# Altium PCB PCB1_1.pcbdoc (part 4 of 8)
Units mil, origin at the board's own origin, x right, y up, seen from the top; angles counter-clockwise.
Board outline 3937.01 x 3346.46 mil, 6 copper layers (Top Layer, Signal-1, SIG, POWER, Signal-4, Bottom Layer), stack 60.565 mil thick; 256 components, 201 nets, 1360 pads, 815 vias.
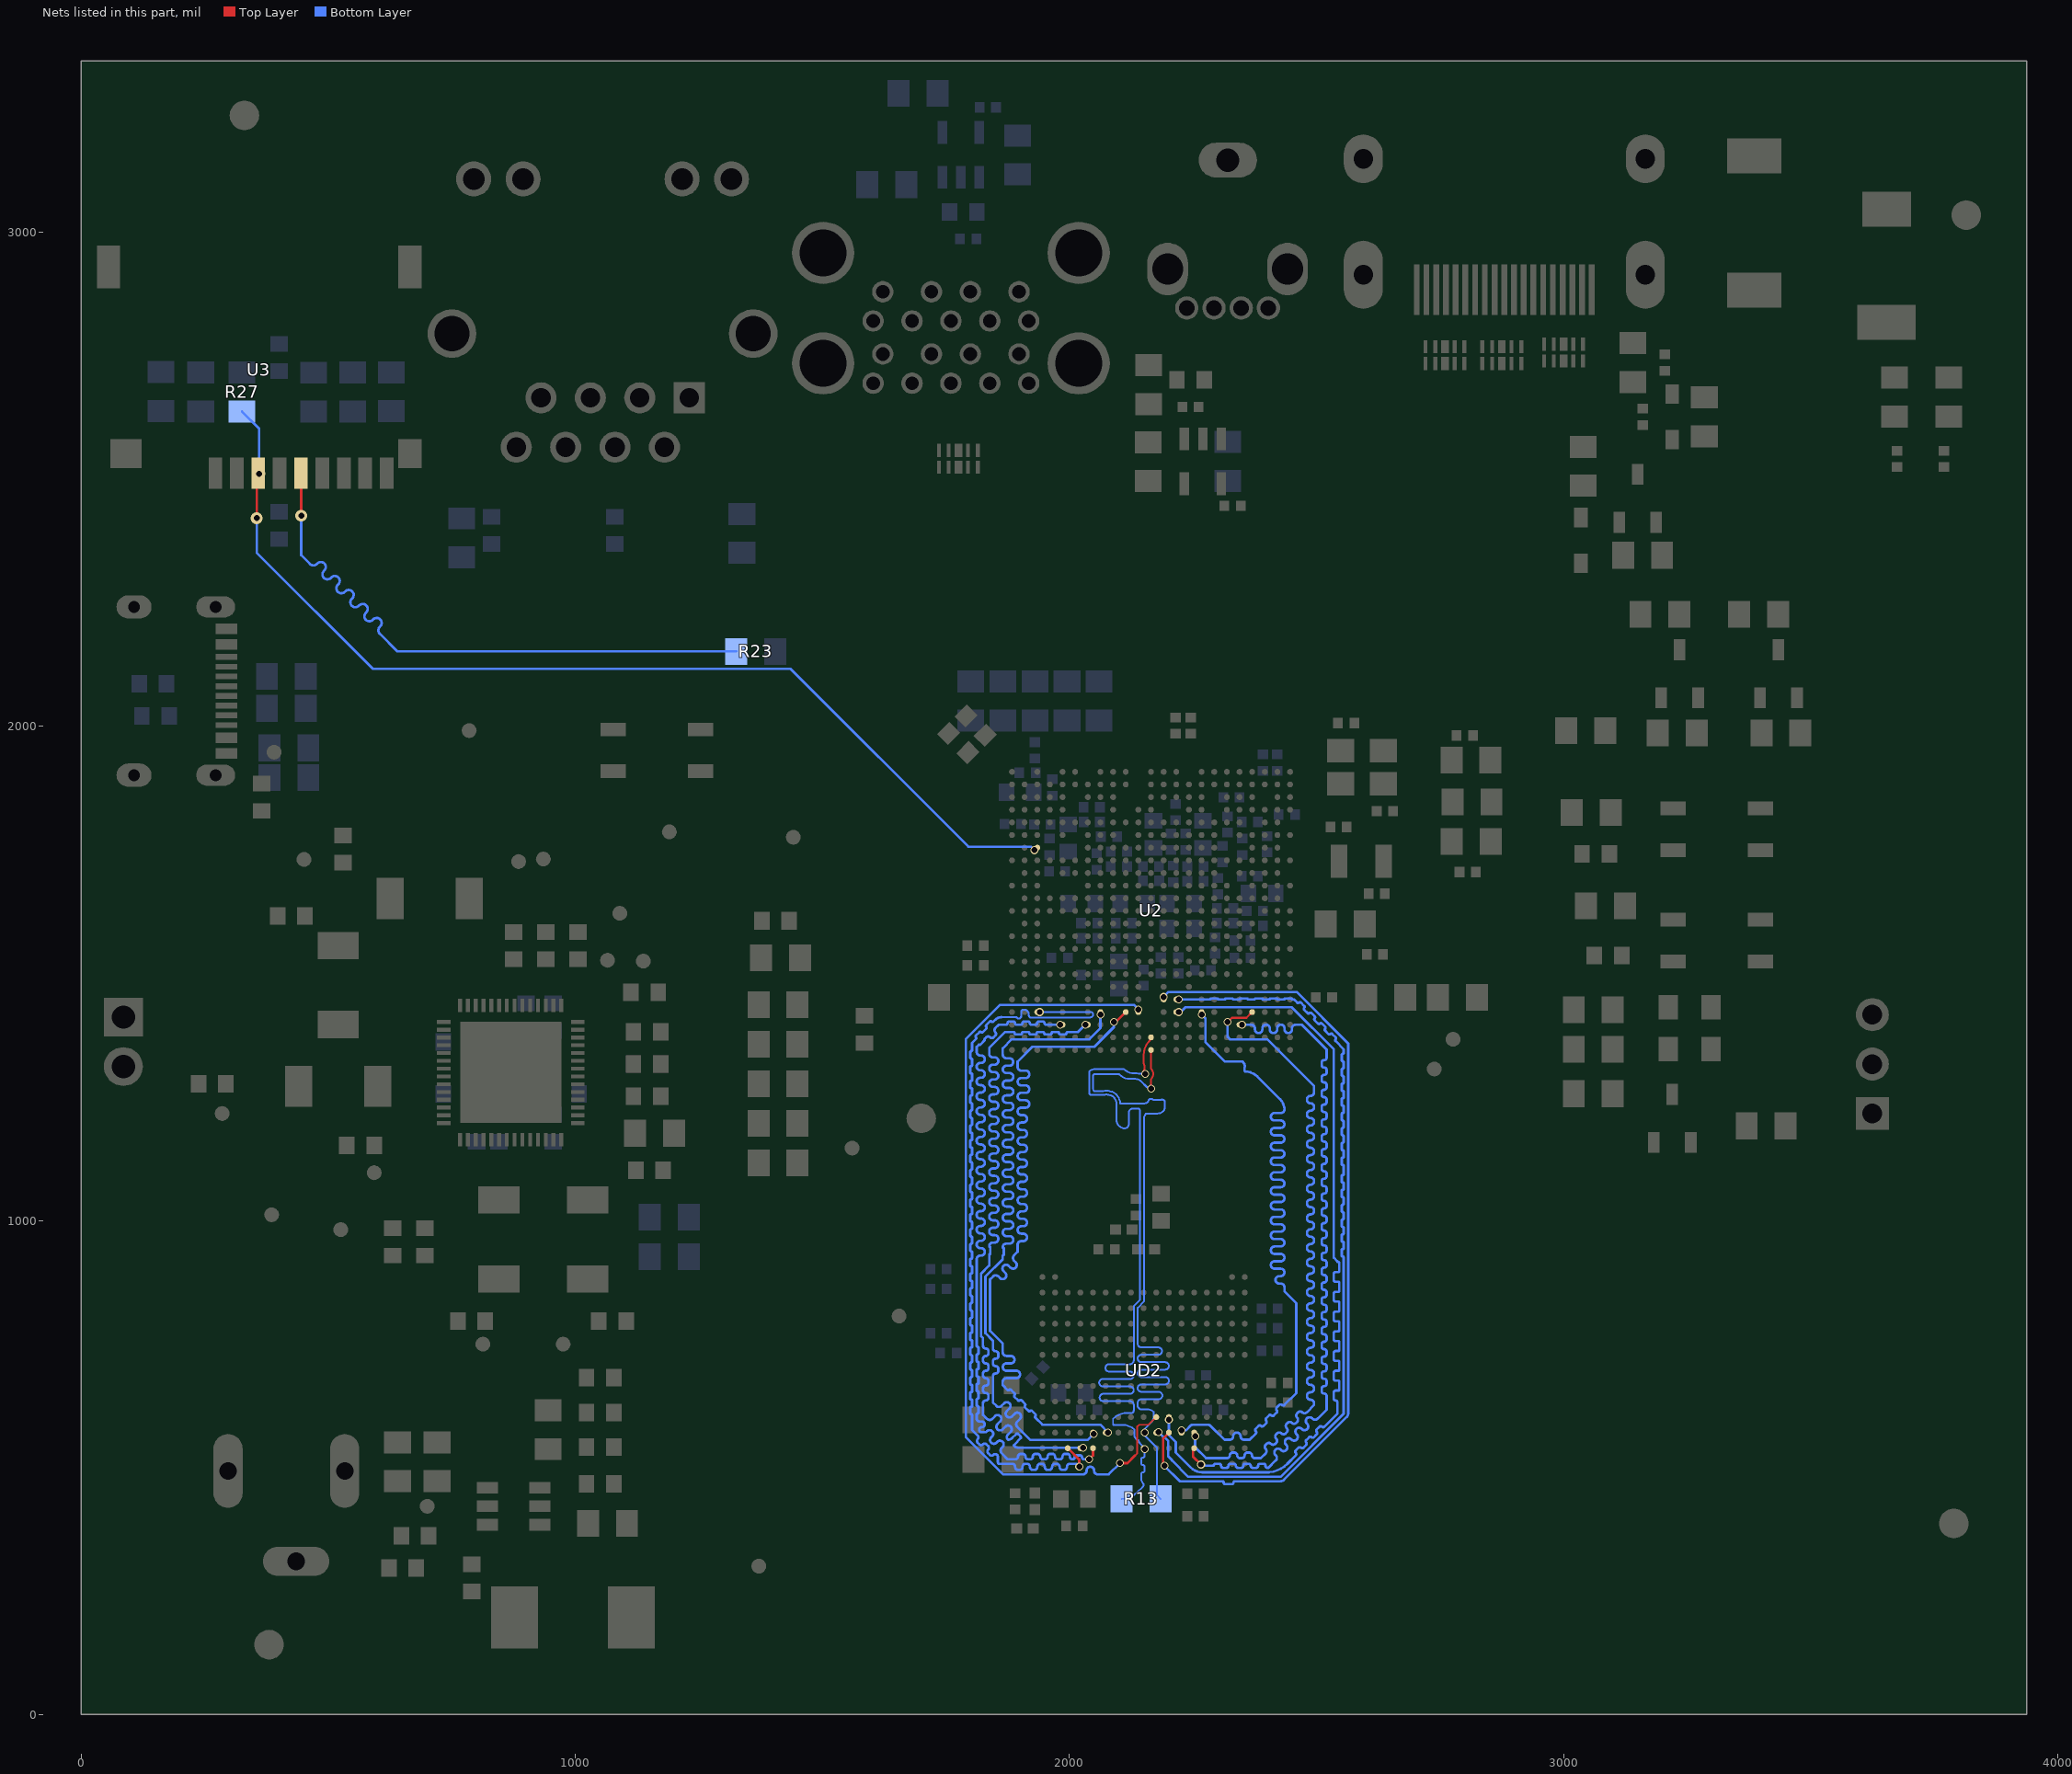
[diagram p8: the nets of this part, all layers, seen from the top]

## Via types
v1: diameter 16, hole 12, Top Layer to Bottom Layer, 426 vias
v2: diameter 24, hole 12, Top Layer to Bottom Layer, 385 vias
v3: diameter 34, hole 12, Top Layer to Bottom Layer, 2 vias
v4: diameter 30, hole 12, Top Layer to Bottom Layer, 2 vias

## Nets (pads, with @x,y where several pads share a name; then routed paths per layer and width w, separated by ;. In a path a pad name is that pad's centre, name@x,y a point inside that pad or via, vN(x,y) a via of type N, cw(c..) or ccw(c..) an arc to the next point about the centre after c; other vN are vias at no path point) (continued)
SA2: U2.AA19 UD2.N2 | length 1699.4
  Top Layer w5: UD2.N2@2252.36,538.98 2250,536.61 2250,522.13 v1(2266.24,505.89)
  Bottom Layer w5: v1(2266.24,505.89) 2268.82,503.31 2291.72,503.31 cw(c2295.89,503.31) 2295.89,507.48 2302.56,507.48 cw(c2302.56,503.31) 2306.72,503.31 ccw(c2310.89,503.31) 2310.89,499.15 2317.56,499.15 ccw(c2317.56,503.31) 2321.72,503.31 cw(c2325.89,503.31) 2325.89,507.48 2332.56,507.48 cw(c2332.56,503.31) 2336.72,503.31 ccw(c2340.89,503.31) 2340.89,499.15 2347.56,499.15 ccw(c2347.56,503.31) 2351.72,503.31 cw(c2355.89,503.31) 2355.89,507.48 2362.56,507.48 cw(c2362.56,503.31) 2366.72,503.31 ccw(c2370.89,503.31) 2370.89,499.15 2377.56,499.15 ccw(c2377.56,503.31) 2381.72,503.31 cw(c2385.89,503.31) 2385.89,507.48 2392.56,507.48 cw(c2392.56,503.31) 2396.72,503.31 ccw(c2400.89,503.31) 2400.89,499.15 2402.69,499.15 2417.48,513.93 ccw(c2412.17,519.24) 2417.48,524.54 2416.95,525.07 cw(c2422.25,530.37) 2427.55,535.68 2428.08,535.15 ccw(c2433.39,540.45) 2438.69,545.75 2438.16,546.28 cw(c2443.46,551.59) 2448.77,556.89 2449.3,556.36 ccw(c2454.6,561.66) 2459.9,566.97 2459.37,567.5 cw(c2464.68,572.8) 2469.98,578.1 2470.51,577.57 ccw(c2475.81,582.88) 2481.12,588.18 2480.59,588.71 cw(c2485.89,594.01) 2491.19,599.32 2491.72,598.79 ccw(c2497.03,604.09) 2502.33,598.79 2520.32,616.78 2520.32,644.5 ccw(c2515.36,644.5) 2515.36,649.46 cw(c2515.36,654.42) 2510.4,654.42 2510.4,659.5 cw(c2515.36,659.5) 2515.36,664.46 ccw(c2515.36,669.42) 2520.32,669.42 2520.32,674.5 ccw(c2515.36,674.5) 2515.36,679.46 cw(c2515.36,684.42) 2510.4,684.42 2510.4,689.5 cw(c2515.36,689.5) 2515.36,694.46 ccw(c2515.36,699.42) 2520.32,699.42 2520.32,704.5 ccw(c2515.36,704.5) 2515.36,709.46 cw(c2515.36,714.42) 2510.4,714.42 2510.4,719.5 cw(c2515.36,719.5) 2515.36,724.46 ccw(c2515.36,729.42) 2520.32,729.42 2520.32,734.5 ccw(c2515.36,734.5) 2515.36,739.46 cw(c2515.36,744.42) 2510.4,744.42 2510.4,749.5 cw(c2515.36,749.5) 2515.36,754.46 ccw(c2515.36,759.42) 2520.32,759.42 2520.32,764.5 ccw(c2515.36,764.5) 2515.36,769.46 cw(c2515.36,774.42) 2510.4,774.42 2510.4,779.5 cw(c2515.36,779.5) 2515.36,784.46 ccw(c2515.36,789.42) 2520.32,789.42 2520.32,794.5 ccw(c2515.36,794.5) 2515.36,799.46 cw(c2515.36,804.42) 2510.4,804.42 2510.4,809.5 cw(c2515.36,809.5) 2515.36,814.46 ccw(c2515.36,819.42) 2520.32,819.42 2520.32,824.5 ccw(c2515.36,824.5) 2515.36,829.46 cw(c2515.36,834.42) 2510.4,834.42 2510.4,839.5 cw(c2515.36,839.5) 2515.36,844.46 ccw(c2515.36,849.42) 2520.32,849.42 2520.32,854.5 ccw(c2515.36,854.5) 2515.36,859.46 cw(c2515.36,864.42) 2510.4,864.42 2510.4,869.5 cw(c2515.36,869.5) 2515.36,874.46 ccw(c2515.36,879.42) 2520.32,879.42 2520.32,884.5 ccw(c2515.36,884.5) 2515.36,889.46 cw(c2515.36,894.42) 2510.4,894.42 2510.4,899.5 cw(c2515.36,899.5) 2515.36,904.46 ccw(c2515.36,909.42) 2520.32,909.42 2520.32,914.5 ccw(c2515.36,914.5) 2515.36,919.46 cw(c2515.36,924.42) 2510.4,924.42 2510.4,929.5 cw(c2515.36,929.5) 2515.36,934.46 ccw(c2515.36,939.42) 2520.32,939.42 2520.32,944.5 ccw(c2515.36,944.5) 2515.36,949.46 cw(c2515.36,954.42) 2510.4,954.42 2510.4,959.5 cw(c2515.36,959.5) 2515.36,964.46 ccw(c2515.36,969.42) 2520.32,969.42 2520.32,974.5 ccw(c2515.36,974.5) 2515.36,979.46 cw(c2515.36,984.42) 2510.4,984.42 2510.4,989.5 cw(c2515.36,989.5) 2515.36,994.46 ccw(c2515.36,999.42) 2520.32,999.42 2520.32,1004.5 ccw(c2515.36,1004.5) 2515.36,1009.46 cw(c2515.36,1014.42) 2510.4,1014.42 2510.4,1019.5 cw(c2515.36,1019.5) 2515.36,1024.46 ccw(c2515.36,1029.42) 2520.32,1029.42 2520.32,1034.5 ccw(c2515.36,1034.5) 2515.36,1039.46 cw(c2515.36,1044.42) 2510.4,1044.42 2510.4,1049.5 cw(c2515.36,1049.5) 2515.36,1054.46 ccw(c2515.36,1059.42) 2520.32,1059.42 2520.32,1064.5 ccw(c2515.36,1064.5) 2515.36,1069.46 cw(c2515.36,1074.42) 2510.4,1074.42 2510.4,1079.5 cw(c2515.36,1079.5) 2515.36,1084.46 ccw(c2515.36,1089.42) 2520.32,1089.42 2520.32,1094.5 ccw(c2515.36,1094.5) 2515.36,1099.46 cw(c2515.36,1104.42) 2510.4,1104.42 2510.4,1109.5 cw(c2515.36,1109.5) 2515.36,1114.46 ccw(c2515.36,1119.42) 2520.32,1119.42 2520.32,1124.5 ccw(c2515.36,1124.5) 2515.36,1129.46 cw(c2515.36,1134.42) 2510.4,1134.42 2510.4,1139.5 cw(c2515.36,1139.5) 2515.36,1144.46 ccw(c2515.36,1149.42) 2520.32,1149.42 2520.32,1154.5 ccw(c2515.36,1154.5) 2515.36,1159.46 cw(c2515.36,1164.42) 2510.4,1164.42 2510.4,1169.5 cw(c2515.36,1169.5) 2515.36,1174.46 ccw(c2515.36,1179.42) 2520.32,1179.42 2520.32,1184.5 ccw(c2515.36,1184.5) 2515.36,1189.46 cw(c2515.36,1194.42) 2510.4,1194.42 2510.4,1199.5 cw(c2515.36,1199.5) 2515.36,1204.46 ccw(c2515.36,1209.42) 2520.32,1209.42 2520.32,1214.5 ccw(c2515.36,1214.5) 2515.36,1219.46 cw(c2515.36,1224.42) 2510.4,1224.42 2510.4,1229.5 cw(c2515.36,1229.5) 2515.36,1234.46 ccw(c2515.36,1239.42) 2520.32,1239.42 2520.32,1244.5 ccw(c2515.36,1244.5) 2515.36,1249.46 cw(c2515.36,1254.42) 2510.4,1254.42 2510.4,1259.5 cw(c2515.36,1259.5) 2515.36,1264.46 ccw(c2515.36,1269.42) 2520.32,1269.42 2520.32,1274.5 ccw(c2515.36,1274.5) 2515.36,1279.46 cw(c2515.36,1284.42) 2510.4,1284.42 2510.4,1289.5 cw(c2515.36,1289.5) 2515.36,1294.46 ccw(c2515.36,1299.42) 2520.32,1299.42 2520.32,1304.5 ccw(c2515.36,1304.5) 2515.36,1309.46 cw(c2515.36,1314.42) 2510.4,1314.42 2510.4,1319.5 cw(c2515.36,1319.5) 2515.36,1324.46 ccw(c2515.36,1329.42) 2520.32,1329.42 2520.32,1345.82 2470,1396.14 2457.82,1396.14 ccw(c2457.82,1388.64) 2450.32,1388.64 2450.32,1386.71 cw(c2442.82,1386.71) 2435.32,1386.71 2435.32,1388.64 ccw(c2427.82,1388.64) 2420.32,1388.64 2420.32,1386.71 cw(c2412.82,1386.71) 2405.32,1386.71 2405.32,1388.64 ccw(c2397.82,1388.64) 2390.32,1388.64 2390.32,1386.71 cw(c2382.82,1386.71) 2375.32,1386.71 2375.32,1388.64 ccw(c2367.82,1388.64) 2367.82,1396.14 v1(2349.13,1396.14)
SA3: U2.Y20 UD2.N3 | length 1693.1
  Top Layer w4: v1(2320.09,1401.55) 2328.69,1410.14 2358.13,1410.14 U2.Y20@2369.72,1421.73
  Bottom Layer w5: v1(2254.34,563.5) 2254.34,540.82 2276.27,518.89 2318.89,518.89 ccw(c2318.89,524.43) 2324.43,524.43 cw(c2329.98,524.43) 2329.98,529.98 2333.89,529.98 cw(c2333.89,524.43) 2339.43,524.43 ccw(c2344.98,524.43) 2344.98,518.89 2348.89,518.89 ccw(c2348.89,524.43) 2354.43,524.43 cw(c2359.98,524.43) 2359.98,529.98 2363.89,529.98 cw(c2363.89,524.43) 2369.43,524.43 ccw(c2374.98,524.43) 2374.98,518.89 2387.43,518.89 2397.11,528.56 ccw(c2392.79,532.88) 2397.11,537.2 cw(c2401.42,541.52) 2397.11,545.84 2399.08,547.81 cw(c2403.39,543.49) 2407.71,547.81 ccw(c2412.03,552.12) 2416.35,547.81 2418.32,549.78 ccw(c2414,554.09) 2418.32,558.41 cw(c2422.64,562.73) 2418.32,567.05 2420.29,569.02 cw(c2424.61,564.7) 2428.93,569.02 ccw(c2433.24,573.34) 2437.56,569.02 2439.53,570.99 ccw(c2435.21,575.31) 2439.53,579.63 cw(c2443.85,583.94) 2439.53,588.26 2441.5,590.23 cw(c2445.82,585.91) 2450.14,590.23 ccw(c2454.46,594.55) 2458.78,590.23 2460.75,592.2 ccw(c2456.43,596.52) 2460.75,600.84 cw(c2465.06,605.16) 2460.75,609.47 2462.72,611.45 cw(c2467.03,607.13) 2471.35,611.45 ccw(c2475.67,615.76) 2479.99,611.45 2495,626.46 2495,629.9 ccw(c2487.79,629.9) 2487.79,637.11 cw(c2487.79,644.31) 2480.59,644.31 2480.59,644.9 cw(c2487.79,644.9) 2487.79,652.11 ccw(c2487.79,659.31) 2495,659.31 2495,659.9 ccw(c2487.79,659.9) 2487.79,667.11 cw(c2487.79,674.31) 2480.59,674.31 2480.59,674.9 cw(c2487.79,674.9) 2487.79,682.11 ccw(c2487.79,689.31) 2495,689.31 2495,689.9 ccw(c2487.79,689.9) 2487.79,697.11 cw(c2487.79,704.31) 2480.59,704.31 2480.59,704.9 cw(c2487.79,704.9) 2487.79,712.11 ccw(c2487.79,719.31) 2495,719.31 2495,719.9 ccw(c2487.79,719.9) 2487.79,727.11 cw(c2487.79,734.31) 2480.59,734.31 2480.59,734.9 cw(c2487.79,734.9) 2487.79,742.11 ccw(c2487.79,749.31) 2495,749.31 2495,749.9 ccw(c2487.79,749.9) 2487.79,757.11 cw(c2487.79,764.31) 2480.59,764.31 2480.59,764.9 cw(c2487.79,764.9) 2487.79,772.11 ccw(c2487.79,779.31) 2495,779.31 2495,779.9 ccw(c2487.79,779.9) 2487.79,787.11 cw(c2487.79,794.31) 2480.59,794.31 2480.59,794.9 cw(c2487.79,794.9) 2487.79,802.11 ccw(c2487.79,809.31) 2495,809.31 2495,809.9 ccw(c2487.79,809.9) 2487.79,817.11 cw(c2487.79,824.31) 2480.59,824.31 2480.59,824.9 cw(c2487.79,824.9) 2487.79,832.11 ccw(c2487.79,839.31) 2495,839.31 2495,839.9 ccw(c2487.79,839.9) 2487.79,847.11 cw(c2487.79,854.31) 2480.59,854.31 2480.59,854.9 cw(c2487.79,854.9) 2487.79,862.11 ccw(c2487.79,869.31) 2495,869.31 2495,869.9 ccw(c2487.79,869.9) 2487.79,877.11 cw(c2487.79,884.31) 2480.59,884.31 2480.59,884.9 cw(c2487.79,884.9) 2487.79,892.11 ccw(c2487.79,899.31) 2495,899.31 2495,899.9 ccw(c2487.79,899.9) 2487.79,907.11 cw(c2487.79,914.31) 2480.59,914.31 2480.59,914.9 cw(c2487.79,914.9) 2487.79,922.11 ccw(c2487.79,929.31) 2495,929.31 2495,929.9 ccw(c2487.79,929.9) 2487.79,937.11 cw(c2487.79,944.31) 2480.59,944.31 2480.59,944.9 cw(c2487.79,944.9) 2487.79,952.11 ccw(c2487.79,959.31) 2495,959.31 2495,959.9 ccw(c2487.79,959.9) 2487.79,967.11 cw(c2487.79,974.31) 2480.59,974.31 2480.59,974.9 cw(c2487.79,974.9) 2487.79,982.11 ccw(c2487.79,989.31) 2495,989.31 2495,989.9 ccw(c2487.79,989.9) 2487.79,997.11 cw(c2487.79,1004.31) 2480.59,1004.31 2480.59,1004.9 cw(c2487.79,1004.9) 2487.79,1012.11 ccw(c2487.79,1019.31) 2495,1019.31 2495,1019.9 ccw(c2487.79,1019.9) 2487.79,1027.11 cw(c2487.79,1034.31) 2480.59,1034.31 2480.59,1034.9 cw(c2487.79,1034.9) 2487.79,1042.11 ccw(c2487.79,1049.31) 2495,1049.31 2495,1049.9 ccw(c2487.79,1049.9) 2487.79,1057.11 cw(c2487.79,1064.31) 2480.59,1064.31 2480.59,1064.9 cw(c2487.79,1064.9) 2487.79,1072.11 ccw(c2487.79,1079.31) 2495,1079.31 2495,1079.9 ccw(c2487.79,1079.9) 2487.79,1087.11 cw(c2487.79,1094.31) 2480.59,1094.31 2480.59,1094.9 cw(c2487.79,1094.9) 2487.79,1102.11 ccw(c2487.79,1109.31) 2495,1109.31 2495,1109.9 ccw(c2487.79,1109.9) 2487.79,1117.11 cw(c2487.79,1124.31) 2480.59,1124.31 2480.59,1124.9 cw(c2487.79,1124.9) 2487.79,1132.11 ccw(c2487.79,1139.31) 2495,1139.31 2495,1139.9 ccw(c2487.79,1139.9) 2487.79,1147.11 cw(c2487.79,1154.31) 2480.59,1154.31 2480.59,1154.9 cw(c2487.79,1154.9) 2487.79,1162.11 ccw(c2487.79,1169.31) 2495,1169.31 2495,1169.9 ccw(c2487.79,1169.9) 2487.79,1177.11 cw(c2487.79,1184.31) 2480.59,1184.31 2480.59,1184.9 cw(c2487.79,1184.9) 2487.79,1192.11 ccw(c2487.79,1199.31) 2495,1199.31 2495,1199.9 ccw(c2487.79,1199.9) 2487.79,1207.11 cw(c2487.79,1214.31) 2480.59,1214.31 2480.59,1214.9 cw(c2487.79,1214.9) 2487.79,1222.11 ccw(c2487.79,1229.31) 2495,1229.31 2495,1229.9 ccw(c2487.79,1229.9) 2487.79,1237.11 cw(c2487.79,1244.31) 2480.59,1244.31 2480.59,1244.9 cw(c2487.79,1244.9) 2487.79,1252.11 ccw(c2487.79,1259.31) 2495,1259.31 2495,1271.46 2400,1366.46 2325,1366.46 2320.09,1371.36 v1(2320.09,1401.55)
SA4: U2.Y16 UD2.M3 | length 1687.8
  Bottom Layer w5: v1(2226.77,575.47) 2236.15,575.47 2246.15,585.47 2246.86,585.47 2247.84,586.46 2282.47,586.46 2283.46,585.47 2284.17,585.47 2313.67,555.97 2324.06,555.97 ccw(c2324.06,563.22) 2331.31,563.22 cw(c2338.56,563.22) 2338.56,570.47 2339.06,570.47 cw(c2339.06,563.22) 2346.31,563.22 ccw(c2353.56,563.22) 2353.56,555.97 2364.52,555.97 2376.96,568.42 ccw(c2374.46,570.92) 2376.96,573.42 cw(c2379.46,575.92) 2376.96,578.42 2382.57,584.03 cw(c2385.07,581.53) 2387.57,584.03 ccw(c2390.07,586.53) 2392.57,584.03 2398.18,589.63 ccw(c2395.68,592.13) 2398.18,594.63 cw(c2400.68,597.13) 2398.18,599.63 2403.78,605.24 cw(c2406.28,602.74) 2408.78,605.24 ccw(c2411.28,607.74) 2413.78,605.24 2419.39,610.85 ccw(c2416.89,613.35) 2419.39,615.85 cw(c2421.89,618.35) 2419.39,620.85 2425,626.45 cw(c2427.5,623.95) 2430,626.45 ccw(c2432.5,628.95) 2435,626.45 2459,650.46 2459,832.46 2435,856.46 2435,864.75 ccw(c2427.5,864.75) 2427.5,872.25 2424.44,872.25 cw(c2424.44,879.75) 2424.44,887.25 2427.5,887.25 ccw(c2427.5,894.75) 2427.5,902.25 2415,902.25 cw(c2415,909.75) 2415,917.25 2427.5,917.25 ccw(c2427.5,924.75) 2427.5,932.25 2415,932.25 cw(c2415,939.75) 2415,947.25 2427.5,947.25 ccw(c2427.5,954.75) 2427.5,962.25 2415,962.25 cw(c2415,969.75) 2415,977.25 2427.5,977.25 ccw(c2427.5,984.75) 2427.5,992.25 2415,992.25 cw(c2415,999.75) 2415,1007.25 2427.5,1007.25 ccw(c2427.5,1014.75) 2427.5,1022.25 2415,1022.25 cw(c2415,1029.75) 2415,1037.25 2427.5,1037.25 ccw(c2427.5,1044.75) 2427.5,1052.25 2415,1052.25 cw(c2415,1059.75) 2415,1067.25 2427.5,1067.25 ccw(c2427.5,1074.75) 2427.5,1082.25 2415,1082.25 cw(c2415,1089.75) 2415,1097.25 2427.5,1097.25 ccw(c2427.5,1104.75) 2427.5,1112.25 2415,1112.25 cw(c2415,1119.75) 2415,1127.25 2427.5,1127.25 ccw(c2427.5,1134.75) 2427.5,1142.25 2415,1142.25 cw(c2415,1149.75) 2415,1157.25 2427.5,1157.25 ccw(c2427.5,1164.75) 2427.5,1172.25 2415,1172.25 cw(c2415,1179.75) 2415,1187.25 2427.5,1187.25 ccw(c2427.5,1194.75) 2427.5,1202.25 2415,1202.25 cw(c2415,1209.75) 2415,1217.25 2427.5,1217.25 ccw(c2427.5,1224.75) 2435,1224.75 ccw(c2406.73,1224.75) 2426.72,1244.74 2380.61,1290.85 ccw(c2355,1265.24) 2355,1301.46 cw(c2367.07,1306.46) 2355,1311.46 ccw(c2342.93,1311.46) 2351.46,1319.99 2350,1321.46 2315,1321.46 2275,1361.46 2275,1409.09 v1(2267.36,1416.73)
SA5: U2.Y10 UD2.F3 | length 1700.3
  Top Layer w5: v1(2090,1401.46) 2093.54,1401.46 U2.Y10@2113.82,1421.73
  Bottom Layer w5: v1(2078.23,570.47) 2062.24,586.46 1945,586.46 1931.1,600.36 cw(c1932.9,602.16) 1931.1,603.97 ccw(c1929.29,605.77) 1931.1,607.58 1924.1,614.57 ccw(c1922.29,612.77) 1920.49,614.58 cw(c1918.69,616.38) 1916.88,614.58 1909.88,621.57 cw(c1911.69,623.38) 1909.88,625.18 ccw(c1908.08,626.99) 1909.88,628.79 1902.89,635.79 ccw(c1901.08,633.98) 1899.28,635.79 cw(c1897.47,637.59) 1895.67,635.79 1888.67,642.79 cw(c1890.47,644.59) 1888.67,646.39 ccw(c1886.87,648.2) 1888.67,650 1881.67,657 ccw(c1879.87,655.2) 1878.06,657 cw(c1876.26,658.81) 1874.46,657 1865,666.46 1865,673.18 cw(c1872.5,673.18) 1872.5,680.68 1892.5,680.68 ccw(c1892.5,688.18) 1892.5,695.68 1872.5,695.68 cw(c1872.5,703.18) 1872.5,710.68 1881.26,710.68 ccw(c1881.26,718.18) 1881.26,725.68 1872.5,725.68 cw(c1872.5,733.18) 1865,733.18 1865,750.46 1839,776.46 1839,880.46 1845.28,886.74 cw(c1850.58,881.43) 1855.89,886.74 1859.27,883.35 ccw(c1864.57,888.66) 1869.88,893.96 1866.49,897.34 cw(c1871.8,902.65) 1877.1,907.95 1880.48,904.57 ccw(c1885.79,909.87) 1891.09,915.17 1887.71,918.56 cw(c1893.01,923.86) 1887.71,929.16 1895,936.46 1895,950.7 cw(c1902.5,950.7) 1902.5,958.2 1906.5,958.2 ccw(c1906.5,965.7) 1906.5,973.2 1902.5,973.2 cw(c1902.5,980.7) 1902.5,988.2 1906.5,988.2 ccw(c1906.5,995.7) 1906.5,1003.2 1902.5,1003.2 cw(c1902.5,1010.7) 1902.5,1018.2 1906.5,1018.2 ccw(c1906.5,1025.7) 1906.5,1033.2 1902.5,1033.2 cw(c1902.5,1040.7) 1902.5,1048.2 1906.5,1048.2 ccw(c1906.5,1055.7) 1906.5,1063.2 1902.5,1063.2 cw(c1902.5,1070.7) 1902.5,1078.2 1906.5,1078.2 ccw(c1906.5,1085.7) 1906.5,1093.2 1902.5,1093.2 cw(c1902.5,1100.7) 1902.5,1108.2 1906.5,1108.2 ccw(c1906.5,1115.7) 1906.5,1123.2 1902.5,1123.2 cw(c1902.5,1130.7) 1902.5,1138.2 1906.5,1138.2 ccw(c1906.5,1145.7) 1906.5,1153.2 1902.5,1153.2 cw(c1902.5,1160.7) 1902.5,1168.2 1906.5,1168.2 ccw(c1906.5,1175.7) 1906.5,1183.2 1902.5,1183.2 cw(c1902.5,1190.7) 1902.5,1198.2 1906.5,1198.2 ccw(c1906.5,1205.7) 1906.5,1213.2 1902.5,1213.2 cw(c1902.5,1220.7) 1902.5,1228.2 1911.17,1228.2 ccw(c1911.17,1235.7) 1911.17,1243.2 1902.5,1243.2 cw(c1902.5,1250.7) 1902.5,1258.2 1911.17,1258.2 ccw(c1911.17,1265.7) 1911.17,1273.2 1902.5,1273.2 cw(c1902.5,1280.7) 1902.5,1288.2 1911.17,1288.2 ccw(c1911.17,1295.7) 1911.17,1303.2 1902.5,1303.2 cw(c1902.5,1310.7) 1895,1310.7 1895,1321.46 1925,1351.46 2050,1351.46 2090,1391.46 v1(2090,1401.46)
SA6: U2.Y8 UD2.E3 | length 1695.1
  Bottom Layer w5: v1(2048.85,567.76) 2036.69,555.6 1920.86,555.6 1894.27,582.19 cw(c1899.57,587.49) 1894.27,592.8 1899.63,598.15 ccw(c1894.32,603.46) 1889.02,608.76 1883.66,603.4 cw(c1878.36,608.7) 1873.05,614.01 1878.41,619.37 ccw(c1873.11,624.67) 1867.81,629.97 1862.45,624.61 cw(c1857.15,629.92) 1851.84,624.61 1845,631.46 1845,684.62 cw(c1850.5,684.62) 1850.5,690.12 ccw(c1850.5,695.62) 1856,695.62 1856,699.62 ccw(c1850.5,699.62) 1850.5,705.12 cw(c1850.5,710.62) 1845,710.62 1845,714.62 cw(c1850.5,714.62) 1850.5,720.12 ccw(c1850.5,725.62) 1856,725.62 1856,729.62 ccw(c1850.5,729.62) 1850.5,735.12 cw(c1850.5,740.62) 1845,740.62 1845,756.67 1830,771.67 1830,886.46 1865,921.46 1865,928.65 cw(c1866,928.65) 1866,929.65 ccw(c1866,930.65) 1867,930.65 1867,943.65 ccw(c1866,943.65) 1866,944.65 cw(c1866,945.65) 1865,945.65 cw(c1872.5,945.65) 1872.5,953.15 1878.68,953.15 ccw(c1878.68,960.65) 1878.68,968.15 1872.5,968.15 cw(c1872.5,975.65) 1872.5,983.15 1878.68,983.15 ccw(c1878.68,990.65) 1878.68,998.15 1872.5,998.15 cw(c1872.5,1005.65) 1872.5,1013.15 1878.68,1013.15 ccw(c1878.68,1020.65) 1878.68,1028.15 1872.5,1028.15 cw(c1872.5,1035.65) 1872.5,1043.15 1878.68,1043.15 ccw(c1878.68,1050.65) 1878.68,1058.15 1872.5,1058.15 cw(c1872.5,1065.65) 1872.5,1073.15 1878.68,1073.15 ccw(c1878.68,1080.65) 1878.68,1088.15 1872.5,1088.15 cw(c1872.5,1095.65) 1872.5,1103.15 1878.68,1103.15 ccw(c1878.68,1110.65) 1878.68,1118.15 1872.5,1118.15 cw(c1872.5,1125.65) 1872.5,1133.15 1878.68,1133.15 ccw(c1878.68,1140.65) 1878.68,1148.15 1872.5,1148.15 cw(c1872.5,1155.65) 1872.5,1163.15 1878.68,1163.15 ccw(c1878.68,1170.65) 1878.68,1178.15 1872.5,1178.15 cw(c1872.5,1185.65) 1872.5,1193.15 1878.68,1193.15 ccw(c1878.68,1200.65) 1878.68,1208.15 1872.5,1208.15 cw(c1872.5,1215.65) 1872.5,1223.15 1878.68,1223.15 ccw(c1878.68,1230.65) 1878.68,1238.15 1872.5,1238.15 cw(c1872.5,1245.65) 1872.5,1253.15 1878.68,1253.15 ccw(c1878.68,1260.65) 1878.68,1268.15 1872.5,1268.15 cw(c1872.5,1275.65) 1872.5,1283.15 1878.68,1283.15 ccw(c1878.68,1290.65) 1878.68,1298.15 1872.5,1298.15 cw(c1872.5,1305.65) 1872.5,1313.15 1878.5,1313.15 ccw(c1878.5,1320.65) 1878.5,1328.15 1872.5,1328.15 cw(c1872.5,1335.65) 1865,1335.65 1865,1348.38 1883.07,1366.46 2040,1366.46 2062.64,1389.09 v1(2062.64,1416.73)
SA7: U2.AA5 UD2.E2 | length 1699
  Top Layer w5: v1(2040,516.46) 2047.64,524.09 UD2.E2@2047.64,538.98
  Bottom Layer w5: v1(1980.87,1396.14) 1952.79,1396.14 cw(c1952.79,1399.3) 1949.63,1399.3 ccw(c1946.48,1399.3) 1946.48,1402.46 1937.79,1402.46 ccw(c1937.79,1399.3) 1934.63,1399.3 cw(c1931.48,1399.3) 1931.48,1396.14 1922.79,1396.14 cw(c1922.79,1399.3) 1919.63,1399.3 ccw(c1916.48,1399.3) 1916.48,1402.46 1907.79,1402.46 ccw(c1907.79,1399.3) 1904.63,1399.3 cw(c1901.48,1399.3) 1901.48,1396.14 1892.88,1396.14 cw(c1892.88,1399.34) 1889.68,1399.34 ccw(c1886.48,1399.34) 1886.48,1402.54 1877.88,1402.54 ccw(c1877.88,1399.34) 1874.68,1399.34 cw(c1871.48,1399.34) 1871.48,1396.14 1856.96,1396.14 1849.63,1388.82 ccw(c1853.38,1385.07) 1849.63,1381.32 cw(c1845.88,1377.57) 1849.63,1373.82 1846.53,1370.71 cw(c1842.78,1374.46) 1839.03,1370.71 ccw(c1835.28,1366.96) 1831.53,1370.71 1828.42,1367.61 ccw(c1829.13,1366.9) 1828.42,1366.19 cw(c1827.71,1365.48) 1828.42,1364.78 1819.23,1355.58 cw(c1818.52,1356.29) 1817.81,1355.58 ccw(c1817.11,1354.88) 1816.4,1355.58 1812,1351.18 1812,1341.29 ccw(c1819.5,1341.29) 1819.5,1333.79 1821,1333.79 cw(c1821,1326.29) 1821,1318.79 1819.5,1318.79 ccw(c1819.5,1311.29) 1819.5,1303.79 1821,1303.79 cw(c1821,1296.29) 1821,1288.79 1819.5,1288.79 ccw(c1819.5,1281.29) 1819.5,1273.79 1821,1273.79 cw(c1821,1266.29) 1821,1258.79 1819.5,1258.79 ccw(c1819.5,1251.29) 1819.5,1243.79 1821,1243.79 cw(c1821,1236.29) 1821,1228.79 1819.5,1228.79 ccw(c1819.5,1221.29) 1819.5,1213.79 1821,1213.79 cw(c1821,1206.29) 1821,1198.79 1819.5,1198.79 ccw(c1819.5,1191.29) 1819.5,1183.79 1821,1183.79 cw(c1821,1176.29) 1821,1168.79 1819.5,1168.79 ccw(c1819.5,1161.29) 1819.5,1153.79 1821,1153.79 cw(c1821,1146.29) 1821,1138.79 1819.5,1138.79 ccw(c1819.5,1131.29) 1819.5,1123.79 1821,1123.79 cw(c1821,1116.29) 1821,1108.79 1819.5,1108.79 ccw(c1819.5,1101.29) 1819.5,1093.79 1821,1093.79 cw(c1821,1086.29) 1821,1078.79 1819.5,1078.79 ccw(c1819.5,1071.29) 1819.5,1063.79 1821,1063.79 cw(c1821,1056.29) 1821,1048.79 1819.5,1048.79 ccw(c1819.5,1041.29) 1819.5,1033.79 1821,1033.79 cw(c1821,1026.29) 1821,1018.79 1819.5,1018.79 ccw(c1819.5,1011.29) 1819.5,1003.79 1821,1003.79 cw(c1821,996.29) 1821,988.79 1819.5,988.79 ccw(c1819.5,981.29) 1819.5,973.79 1821,973.79 cw(c1821,966.29) 1821,958.79 1819.5,958.79 ccw(c1819.5,951.29) 1819.5,943.79 1821,943.79 cw(c1821,936.29) 1821,928.79 1819.5,928.79 ccw(c1819.5,921.29) 1812,921.29 1812,746.13 ccw(c1814,746.13) 1814,744.13 cw(c1814,742.13) 1816,742.13 1816,731.13 cw(c1814,731.13) 1814,729.13 ccw(c1814,727.13) 1812,727.13 1812,716.13 ccw(c1814,716.13) 1814,714.13 cw(c1814,712.13) 1816,712.13 1816,701.13 cw(c1814,701.13) 1814,699.13 ccw(c1814,697.13) 1812,697.13 1812,686.13 ccw(c1814,686.13) 1814,684.13 cw(c1814,682.13) 1816,682.13 1816,671.13 cw(c1814,671.13) 1814,669.13 ccw(c1814,667.13) 1812,667.13 1812,656.13 ccw(c1814,656.13) 1814,654.13 cw(c1814,652.13) 1816,652.13 1816,641.13 cw(c1814,641.13) 1814,639.13 ccw(c1814,637.13) 1812,637.13 1812,626.13 ccw(c1814,626.13) 1814,624.13 cw(c1814,622.13) 1816,622.13 1816,611.13 cw(c1814,611.13) 1814,609.13 ccw(c1814,607.13) 1812,607.13 1812,598.96 ccw(c1818.04,598.96) 1813.77,594.69 ccw(c1818.04,598.96) 1818.04,592.92 1822.63,592.92 cw(c1822.63,587.19) 1826.68,591.24 cw(c1822.63,587.19) 1828.36,587.19 cw(c1822.63,587.19) 1826.68,583.14 cw(c1822.63,587.19) 1822.63,581.46 1822.12,581.46 ccw(c1822.12,576.35) 1818.5,579.96 ccw(c1822.12,576.35) 1817.01,576.35 ccw(c1821.58,576.35) 1818.35,573.11 ccw(c1822.88,577.64) 1822.88,571.23 1830.83,571.23 1832.84,573.24 cw(c1838.14,567.94) 1843.44,562.63 1841.44,560.63 ccw(c1846.74,555.32) 1852.04,550.02 1854.05,552.03 cw(c1859.35,546.72) 1864.66,541.42 1862.65,539.41 ccw(c1867.95,534.11) 1862.65,528.81 1875,516.46 1890.29,516.46 ccw(c1890.29,521.96) 1895.79,521.96 cw(c1901.29,521.96) 1901.29,527.46 1905.29,527.46 cw(c1905.29,521.96) 1910.79,521.96 ccw(c1916.29,521.96) 1916.29,516.46 1920.29,516.46 ccw(c1920.29,521.96) 1925.79,521.96 cw(c1931.29,521.96) 1931.29,527.46 1935.29,527.46 cw(c1935.29,521.96) 1940.79,521.96 ccw(c1946.29,521.96) 1946.29,516.46 1950.29,516.46 ccw(c1950.29,521.96) 1955.79,521.96 cw(c1961.29,521.96) 1961.29,527.46 1965.29,527.46 cw(c1965.29,521.96) 1970.79,521.96 ccw(c1976.29,521.96) 1976.29,516.46 1980.29,516.46 ccw(c1980.29,521.96) 1985.79,521.96 cw(c1991.29,521.96) 1991.29,527.46 1995.29,527.46 cw(c1995.29,521.96) 2000.79,521.96 ccw(c2006.29,521.96) 2006.29,516.46 2006.4,516.46 ccw(c2006.4,520.47) 2010.41,520.47 cw(c2014.43,520.47) 2014.43,524.48 2021.4,524.48 cw(c2021.4,520.47) 2025.41,520.47 ccw(c2029.43,520.47) 2029.43,516.46 v1(2040,516.46)
SA8: U2.AA7 UD2.D2 | length 1688.9
  Bottom Layer w5: v1(2027.24,539.91) 1897.28,539.91 cw(c1897.28,553.74) 1887.5,543.96 cw(c1890.39,543.96) 1888.35,546 1901.9,559.56 ccw(c1896.42,559.56) 1900.29,563.43 1895.97,567.76 ccw(c1894.23,566.01) 1894.23,568.48 ccw(c1894.23,565.46) 1892.09,567.59 1884.01,559.51 cw(c1875.48,568.05) 1875.48,555.98 cw(c1880.78,561.28) 1875.48,566.58 1881.01,572.11 ccw(c1875.7,577.42) 1870.4,582.72 1864.87,577.19 cw(c1859.57,582.49) 1854.27,587.8 1859.79,593.33 ccw(c1854.49,598.63) 1849.19,603.93 1843.66,598.4 cw(c1838.36,603.71) 1833.05,598.4 1825,606.46 1825,630.12 cw(c1830.5,630.12) 1830.5,635.62 ccw(c1830.5,641.12) 1836,641.12 1836,645.12 ccw(c1830.5,645.12) 1830.5,650.62 cw(c1830.5,656.12) 1825,656.12 1825,660.12 cw(c1830.5,660.12) 1830.5,665.62 ccw(c1830.5,671.12) 1836,671.12 1836,675.12 ccw(c1830.5,675.12) 1830.5,680.62 cw(c1830.5,686.12) 1825,686.12 1825,690.12 cw(c1830.5,690.12) 1830.5,695.62 ccw(c1830.5,701.12) 1836,701.12 1836,705.12 ccw(c1830.5,705.12) 1830.5,710.62 cw(c1830.5,716.12) 1825,716.12 1825,720.12 cw(c1830.5,720.12) 1830.5,725.62 ccw(c1830.5,731.12) 1836,731.12 1836,735.12 ccw(c1830.5,735.12) 1830.5,740.62 cw(c1830.5,746.12) 1825,746.12 1825,761.46 1821,765.46 1821,892.46 1837.5,908.96 1837.5,930.72 cw(c1838.5,930.72) 1838.5,931.72 ccw(c1838.5,932.72) 1839.5,932.72 1839.5,945.72 ccw(c1838.5,945.72) 1838.5,946.72 cw(c1838.5,947.72) 1837.5,947.72 cw(c1845,947.72) 1845,955.22 1848.5,955.22 ccw(c1848.5,962.72) 1848.5,970.22 1845,970.22 cw(c1845,977.72) 1845,985.22 1848.5,985.22 ccw(c1848.5,992.72) 1848.5,1000.22 1845,1000.22 cw(c1845,1007.72) 1845,1015.22 1848.5,1015.22 ccw(c1848.5,1022.72) 1848.5,1030.22 1845,1030.22 cw(c1845,1037.72) 1845,1045.22 1848.5,1045.22 ccw(c1848.5,1052.72) 1848.5,1060.22 1845,1060.22 cw(c1845,1067.72) 1845,1075.22 1848.5,1075.22 ccw(c1848.5,1082.72) 1848.5,1090.22 1845,1090.22 cw(c1845,1097.72) 1845,1105.22 1848.5,1105.22 ccw(c1848.5,1112.72) 1848.5,1120.22 1845,1120.22 cw(c1845,1127.72) 1845,1135.22 1848.5,1135.22 ccw(c1848.5,1142.72) 1848.5,1150.22 1845,1150.22 cw(c1845,1157.72) 1845,1165.22 1848.5,1165.22 ccw(c1848.5,1172.72) 1848.5,1180.22 1845,1180.22 cw(c1845,1187.72) 1845,1195.22 1848.5,1195.22 ccw(c1848.5,1202.72) 1848.5,1210.22 1845,1210.22 cw(c1845,1217.72) 1845,1225.22 1848.5,1225.22 ccw(c1848.5,1232.72) 1848.5,1240.22 1845,1240.22 cw(c1845,1247.72) 1845,1255.22 1848.5,1255.22 ccw(c1848.5,1262.72) 1848.5,1270.22 1845,1270.22 cw(c1845,1277.72) 1845,1285.22 1848.5,1285.22 ccw(c1848.5,1292.72) 1848.5,1300.22 1845,1300.22 cw(c1845,1307.72) 1845,1315.22 1848.5,1315.22 ccw(c1848.5,1322.72) 1848.5,1330.22 1845,1330.22 cw(c1845,1337.72) 1837.5,1337.72 1837.5,1348.96 1870,1381.46 1886.28,1381.46 cw(c1886.28,1378.96) 1888.78,1378.96 ccw(c1891.28,1378.96) 1891.28,1376.46 1901.28,1376.46 ccw(c1901.28,1378.96) 1903.78,1378.96 cw(c1906.28,1378.96) 1906.28,1381.46 1916.28,1381.46 cw(c1916.28,1378.96) 1918.78,1378.96 ccw(c1921.28,1378.96) 1921.28,1376.46 1931.28,1376.46 ccw(c1931.28,1378.96) 1933.78,1378.96 cw(c1936.28,1378.96) 1936.28,1381.46 1946.28,1381.46 cw(c1946.28,1378.96) 1948.78,1378.96 ccw(c1951.28,1378.96) 1951.28,1376.46 1961.28,1376.46 ccw(c1961.28,1378.96) 1963.78,1378.96 cw(c1966.28,1378.96) 1966.28,1381.46 1976.28,1381.46 cw(c1976.28,1378.96) 1978.78,1378.96 ccw(c1981.28,1378.96) 1981.28,1376.46 1991.28,1376.46 ccw(c1991.28,1378.96) 1993.78,1378.96 cw(c1996.28,1378.96) 1996.28,1381.46 2017.36,1381.46 v1(2032.05,1396.14)
SA9: U2.Y3 UD2.C2 | length 1697.4
  Top Layer w5: UD2.C2@1996.46,538.98 2019.77,515.66 v1(2019.77,501.46)
  Bottom Layer w3.5: 1920,1410.71 2042.12,1410.71 2042.87,1411.46 ccw(c2042.87,1416.59) 2046.5,1412.96 ccw(c2042.87,1416.59) 2048.01,1416.59 ccw(c2042.87,1416.59) 2046.5,1420.23 ccw(c2042.87,1416.59) 2042.87,1421.73 v1(1939.69,1421.73)
  Bottom Layer w4: 1862.07,1411.46 1890.51,1411.46 cw(c1890.51,1406.63) 1893.93,1410.04 ccw(c1897.34,1413.46) 1897.34,1408.63 ccw(c1897.34,1413.46) 1900.76,1410.04 ccw(c1897.34,1413.46) 1902.17,1413.46 1902.17,1421.63 cw(c1907,1421.63) 1903.59,1425.04 cw(c1907,1421.63) 1907,1426.46 1908.64,1426.46 cw(c1908.64,1417.92) 1914.67,1423.96 cw(c1908.64,1417.92) 1917.17,1417.92 1917.17,1417.54 ccw(c1926.83,1417.54) 1920,1410.71
  Bottom Layer w5: 1862.07,1411.46 ccw(c1862.07,1394.39) 1850,1406.46 1845.87,1402.33 cw(c1844.06,1404.15) 1842.24,1402.33 ccw(c1840.42,1400.51) 1838.6,1402.33 1831.63,1395.36 ccw(c1833.45,1393.54) 1831.63,1391.72 cw(c1829.81,1389.91) 1831.63,1388.09 1824.66,1381.12 cw(c1822.84,1382.93) 1821.02,1381.12 ccw(c1819.21,1379.3) 1817.39,1381.12 1810.42,1374.15 ccw(c1812.24,1372.33) 1810.42,1370.51 cw(c1808.6,1368.69) 1810.42,1366.87 1803,1359.46 1803,1344.57 cw(c1801,1344.57) 1801,1342.57 ccw(c1801,1340.57) 1799,1340.57 1799,1329.57 ccw(c1801,1329.57) 1801,1327.57 cw(c1801,1325.57) 1803,1325.57 1803,1314.57 cw(c1801,1314.57) 1801,1312.57 ccw(c1801,1310.57) 1799,1310.57 1799,1299.57 ccw(c1801,1299.57) 1801,1297.57 cw(c1801,1295.57) 1803,1295.57 1803,1284.57 cw(c1801,1284.57) 1801,1282.57 ccw(c1801,1280.57) 1799,1280.57 1799,1269.57 ccw(c1801,1269.57) 1801,1267.57 cw(c1801,1265.57) 1803,1265.57 1803,1254.57 cw(c1801,1254.57) 1801,1252.57 ccw(c1801,1250.57) 1799,1250.57 1799,1239.57 ccw(c1801,1239.57) 1801,1237.57 cw(c1801,1235.57) 1803,1235.57 1803,1224.57 cw(c1801,1224.57) 1801,1222.57 ccw(c1801,1220.57) 1799,1220.57 1799,1209.57 ccw(c1801,1209.57) 1801,1207.57 cw(c1801,1205.57) 1803,1205.57 1803,1194.57 cw(c1801,1194.57) 1801,1192.57 ccw(c1801,1190.57) 1799,1190.57 1799,1179.57 ccw(c1801,1179.57) 1801,1177.57 cw(c1801,1175.57) 1803,1175.57 1803,1164.57 cw(c1801,1164.57) 1801,1162.57 ccw(c1801,1160.57) 1799,1160.57 1799,1149.57 ccw(c1801,1149.57) 1801,1147.57 cw(c1801,1145.57) 1803,1145.57 1803,1134.57 cw(c1801,1134.57) 1801,1132.57 ccw(c1801,1130.57) 1799,1130.57 1799,1119.57 ccw(c1801,1119.57) 1801,1117.57 cw(c1801,1115.57) 1803,1115.57 1803,1104.57 cw(c1801,1104.57) 1801,1102.57 ccw(c1801,1100.57) 1799,1100.57 1799,1089.57 ccw(c1801,1089.57) 1801,1087.57 cw(c1801,1085.57) 1803,1085.57 1803,1074.57 cw(c1801,1074.57) 1801,1072.57 ccw(c1801,1070.57) 1799,1070.57 1799,1059.57 ccw(c1801,1059.57) 1801,1057.57 cw(c1801,1055.57) 1803,1055.57 1803,1044.57 cw(c1801,1044.57) 1801,1042.57 ccw(c1801,1040.57) 1799,1040.57 1799,1029.57 ccw(c1801,1029.57) 1801,1027.57 cw(c1801,1025.57) 1803,1025.57 1803,1014.57 cw(c1801,1014.57) 1801,1012.57 ccw(c1801,1010.57) 1799,1010.57 1799,999.57 ccw(c1801,999.57) 1801,997.57 cw(c1801,995.57) 1803,995.57 1803,984.57 cw(c1801,984.57) 1801,982.57 ccw(c1801,980.57) 1799,980.57 1799,969.57 ccw(c1801,969.57) 1801,967.57 cw(c1801,965.57) 1803,965.57 1803,954.57 cw(c1801,954.57) 1801,952.57 ccw(c1801,950.57) 1799,950.57 1799,939.57 ccw(c1801,939.57) 1801,937.57 cw(c1801,935.57) 1803,935.57 1803,924.57 cw(c1801,924.57) 1801,922.57 ccw(c1801,920.57) 1799,920.57 1799,909.57 ccw(c1801,909.57) 1801,907.57 cw(c1801,905.57) 1803,905.57 1803,894.57 cw(c1801,894.57) 1801,892.57 ccw(c1801,890.57) 1799,890.57 1799,879.57 ccw(c1801,879.57) 1801,877.57 cw(c1801,875.57) 1803,875.57 1803,864.57 cw(c1801,864.57) 1801,862.57 ccw(c1801,860.57) 1799,860.57 1799,849.57 ccw(c1801,849.57) 1801,847.57 cw(c1801,845.57) 1803,845.57 1803,834.57 cw(c1801,834.57) 1801,832.57 ccw(c1801,830.57) 1799,830.57 1799,819.57 ccw(c1801,819.57) 1801,817.57 cw(c1801,815.57) 1803,815.57 1803,804.57 cw(c1801,804.57) 1801,802.57 ccw(c1801,800.57) 1799,800.57 1799,789.57 ccw(c1801,789.57) 1801,787.57 cw(c1801,785.57) 1803,785.57 1803,774.57 cw(c1801,774.57) 1801,772.57 ccw(c1801,770.57) 1799,770.57 1799,759.57 ccw(c1801,759.57) 1801,757.57 cw(c1801,755.57) 1803,755.57 1803,744.57 cw(c1801,744.57) 1801,742.57 ccw(c1801,740.57) 1799,740.57 1799,729.57 ccw(c1801,729.57) 1801,727.57 cw(c1801,725.57) 1803,725.57 1803,714.57 cw(c1801,714.57) 1801,712.57 ccw(c1801,710.57) 1799,710.57 1799,699.57 ccw(c1801,699.57) 1801,697.57 cw(c1801,695.57) 1803,695.57 1803,684.57 cw(c1801,684.57) 1801,682.57 ccw(c1801,680.57) 1799,680.57 1799,669.57 ccw(c1801,669.57) 1801,667.57 cw(c1801,665.57) 1803,665.57 1803,654.57 cw(c1801,654.57) 1801,652.57 ccw(c1801,650.57) 1799,650.57 1799,639.57 ccw(c1801,639.57) 1801,637.57 cw(c1801,635.57) 1803,635.57 1803,624.57 cw(c1801,624.57) 1801,622.57 ccw(c1801,620.57) 1799,620.57 1799,609.57 ccw(c1801,609.57) 1801,607.57 cw(c1801,605.57) 1803,605.57 1803,575.73 1814.21,564.51 cw(c1810.58,560.88) 1814.21,557.24 ccw(c1817.85,553.61) 1814.21,549.97 1817.55,546.64 ccw(c1821.18,550.27) 1824.82,546.64 cw(c1828.46,543) 1832.09,546.64 1835.43,543.3 cw(c1831.79,539.67) 1835.43,536.03 ccw(c1839.06,532.39) 1835.43,528.76 1838.76,525.42 ccw(c1842.4,529.06) 1846.03,525.42 cw(c1849.67,521.79) 1853.31,525.42 cw(c1849.22,521.33) 1855,521.33 1855,511.11 ccw(c1859.66,511.11) 1856.36,507.82 ccw(c1857.24,508.7) 1857.24,507.46 1883.67,507.46 cw(c1883.67,501.24) 1889.89,501.24 ccw(c1896.1,501.24) 1896.1,495.03 1898.67,495.03 ccw(c1898.67,501.24) 1904.89,501.24 cw(c1911.1,501.24) 1911.1,507.46 1913.67,507.46 cw(c1913.67,501.24) 1919.89,501.24 ccw(c1926.1,501.24) 1926.1,495.03 1928.67,495.03 ccw(c1928.67,501.24) 1934.89,501.24 cw(c1941.1,501.24) 1941.1,507.46 1943.67,507.46 cw(c1943.67,501.24) 1949.89,501.24 ccw(c1956.1,501.24) 1956.1,495.03 1958.67,495.03 ccw(c1958.67,501.24) 1964.89,501.24 cw(c1971.1,501.24) 1971.1,507.46 1973.67,507.46 cw(c1973.67,501.24) 1979.89,501.24 ccw(c1986.1,501.24) 1986.1,495.03 1988.67,495.03 ccw(c1988.67,501.24) 1994.89,501.24 cw(c2001.1,501.24) 2001.1,507.46 2013.77,507.46 v1(2019.77,501.46)
SCKE0: U2.W14 UD2.K3 | length 1699.9
  Bottom Layer w5: v1(2180.03,571.14) 2189.63,561.55 2192.18,561.55 2200,553.73 2200,522.16 2207.43,514.73 2207.43,514.02 2240.31,481.15 2427.42,481.15 2555,608.73 2555,924.85 ccw(c2553,924.85) 2553,926.85 cw(c2553,928.85) 2551,928.85 2551,939.85 cw(c2553,939.85) 2553,941.85 ccw(c2553,943.85) 2555,943.85 2555,954.85 ccw(c2553,954.85) 2553,956.85 cw(c2553,958.85) 2551,958.85 2551,969.85 cw(c2553,969.85) 2553,971.85 ccw(c2553,973.85) 2555,973.85 2555,984.85 ccw(c2553,984.85) 2553,986.85 cw(c2553,988.85) 2551,988.85 2551,999.85 cw(c2553,999.85) 2553,1001.85 ccw(c2553,1003.85) 2555,1003.85 2555,1014.85 ccw(c2553,1014.85) 2553,1016.85 cw(c2553,1018.85) 2551,1018.85 2551,1029.85 cw(c2553,1029.85) 2553,1031.85 ccw(c2553,1033.85) 2555,1033.85 2555,1044.85 ccw(c2553,1044.85) 2553,1046.85 cw(c2553,1048.85) 2551,1048.85 2551,1059.85 cw(c2553,1059.85) 2553,1061.85 ccw(c2553,1063.85) 2555,1063.85 2555,1074.85 ccw(c2553,1074.85) 2553,1076.85 cw(c2553,1078.85) 2551,1078.85 2551,1089.85 cw(c2553,1089.85) 2553,1091.85 ccw(c2553,1093.85) 2555,1093.85 2555,1110.18 ccw(c2553,1110.18) 2553,1112.18 cw(c2553,1114.18) 2551,1114.18 2551,1125.18 cw(c2553,1125.18) 2553,1127.18 ccw(c2553,1129.18) 2555,1129.18 2555,1140.18 ccw(c2553,1140.18) 2553,1142.18 cw(c2553,1144.18) 2551,1144.18 2551,1155.18 cw(c2553,1155.18) 2553,1157.18 ccw(c2553,1159.18) 2555,1159.18 2555,1170.18 ccw(c2553,1170.18) 2553,1172.18 cw(c2553,1174.18) 2551,1174.18 2551,1185.18 cw(c2553,1185.18) 2553,1187.18 ccw(c2553,1189.18) 2555,1189.18 2555,1200.18 ccw(c2553,1200.18) 2553,1202.18 cw(c2553,1204.18) 2551,1204.18 2551,1215.18 cw(c2553,1215.18) 2553,1217.18 ccw(c2553,1219.18) 2555,1219.18 2555,1230.18 ccw(c2553,1230.18) 2553,1232.18 cw(c2553,1234.18) 2551,1234.18 2551,1245.18 cw(c2553,1245.18) 2553,1247.18 ccw(c2553,1249.18) 2555,1249.18 2555,1260.18 ccw(c2553,1260.18) 2553,1262.18 cw(c2553,1264.18) 2551,1264.18 2551,1275.18 cw(c2553,1275.18) 2553,1277.18 ccw(c2553,1279.18) 2555,1279.18 2555,1290.18 ccw(c2553,1290.18) 2553,1292.18 cw(c2553,1294.18) 2551,1294.18 2551,1305.18 cw(c2553,1305.18) 2553,1307.18 ccw(c2553,1309.18) 2555,1309.18 2555,1320.18 ccw(c2553,1320.18) 2553,1322.18 cw(c2553,1324.18) 2551,1324.18 2551,1335.18 cw(c2553,1335.18) 2553,1337.18 ccw(c2553,1339.18) 2555,1339.18 2555,1346.46 2538.68,1362.78 cw(c2540.61,1364.71) 2538.68,1366.64 ccw(c2536.75,1368.58) 2538.68,1370.51 2531.93,1377.25 ccw(c2530,1375.32) 2528.07,1377.25 cw(c2526.14,1379.18) 2524.21,1377.25 2517.46,1383.99 cw(c2519.4,1385.92) 2517.46,1387.86 ccw(c2515.53,1389.79) 2517.46,1391.72 2510.72,1398.46 ccw(c2508.79,1396.53) 2506.86,1398.46 cw(c2504.93,1400.4) 2502.99,1398.46 2496.25,1405.21 cw(c2498.18,1407.14) 2496.25,1409.07 ccw(c2494.32,1411) 2496.25,1412.93 2489.51,1419.68 ccw(c2487.58,1417.74) 2485.64,1419.68 cw(c2483.71,1421.61) 2481.78,1419.68 2475.04,1426.42 cw(c2476.97,1428.35) 2475.04,1430.28 ccw(c2473.11,1432.22) 2475.04,1434.15 2468.29,1440.89 ccw(c2466.36,1438.96) 2464.43,1440.89 cw(c2462.5,1442.82) 2460.57,1440.89 2454.13,1447.32 2451.32,1447.32 cw(c2451.32,1448.32) 2450.32,1448.32 ccw(c2449.32,1448.32) 2449.32,1449.32 2436.32,1449.32 ccw(c2436.32,1448.32) 2435.32,1448.32 cw(c2434.32,1448.32) 2434.32,1447.32 2421.32,1447.32 cw(c2421.32,1448.32) 2420.32,1448.32 ccw(c2419.32,1448.32) 2419.32,1449.32 2406.32,1449.32 ccw(c2406.32,1448.32) 2405.32,1448.32 cw(c2404.32,1448.32) 2404.32,1447.32 2391.32,1447.32 cw(c2391.32,1448.32) 2390.32,1448.32 ccw(c2389.32,1448.32) 2389.32,1449.32 2376.32,1449.32 ccw(c2376.32,1448.32) 2375.32,1448.32 cw(c2374.32,1448.32) 2374.32,1447.32 2361.32,1447.32 cw(c2361.32,1448.32) 2360.32,1448.32 ccw(c2359.32,1448.32) 2359.32,1449.32 2346.32,1449.32 ccw(c2346.32,1448.32) 2345.32,1448.32 cw(c2344.32,1448.32) 2344.32,1447.32 2331.32,1447.32 cw(c2331.32,1448.32) 2330.32,1448.32 ccw(c2329.32,1448.32) 2329.32,1449.32 2316.32,1449.32 ccw(c2316.32,1448.32) 2315.32,1448.32 cw(c2314.32,1448.32) 2314.32,1447.32 2301.32,1447.32 cw(c2301.32,1448.32) 2300.32,1448.32 ccw(c2299.32,1448.32) 2299.32,1449.32 2286.32,1449.32 ccw(c2286.32,1448.32) 2285.32,1448.32 cw(c2284.32,1448.32) 2284.32,1447.32 v1(2221.18,1447.32)
SCKE1: U2.Y11 UD2.K4 | length 1702
  Top Layer w3.5: 2132.81,524.27 2137.28,528.74 2137.28,582.96 2140.78,586.46 2160.08,586.46 UD2.K4@2175.59,601.97
  Top Layer w5: v1(2102.36,508.81) 2117.36,508.81 2132.81,524.27
  Bottom Layer w5: v1(2102.36,508.81) 2079.57,486.03 2057.22,486.03 cw(c2057.22,493.53) 2049.72,493.53 2049.72,493.96 ccw(c2042.22,493.96) 2034.72,493.96 2034.72,493.53 cw(c2027.22,493.53) 2027.22,486.03 1865.43,486.03 1790,561.46 1790,1366.46 1859.78,1436.23 2130.22,1436.23 2139.41,1427.05 v1(2139.41,1426.73)
SCKN: R13.2 U2.AB12 UD2.J2 | length 1693.8
  Top Layer w3.7: v1(2153.29,1296.82) 2153.29,1298.95 2150,1302.24 ccw(c2135.54,1310.18) 2150,1318.12 2150,1334.34 cw(c2191.33,1334.34) 2162.1,1363.56 ccw(c2155.12,1370.55) U2.AB12@2165,1370.55
  Bottom Layer w3.7: R13.2@2105.63,436.46 ccw(c2105.63,480.08) 2136.48,449.23 2148.33,461.08 ccw(c2144.28,465.12) 2150,465.12 ccw(c2146.78,465.12) 2149.06,467.4 cw(c2157.57,475.91) 2145.53,475.91 ; 2145.54,475.93 cw(c2147.5,477.49) 2145,477.49 2145,486.48 cw(c2148.48,486.48) 2148.48,489.96 ccw(c2148.48,493.44) 2151.96,493.44 2151.96,501.48 ccw(c2148.48,501.48) 2148.48,504.96 cw(c2148.48,508.44) 2145,508.44 2145,516.48 cw(c2148.48,516.48) 2148.48,519.96 ccw(c2148.48,523.44) 2151.96,523.44 v1(2151.96,537.22) ccw(c2146.45,537.22) 2150.35,541.11 2142.49,548.96 cw(c2148.51,554.98) 2140,554.98 cw(c2140,561.21) 2135.6,556.81 cw(c2146.83,568.03) 2130.95,568.03 2130.95,576.84 ccw(c2109.1,554.98) 2109.1,585.89 2090.1,585.89 cw(c2090.1,587.89) 2088.1,587.89 2088.1,598.35 cw(c2116.83,569.63) 2116.83,610.25 2125.17,610.25 ccw(c2125.17,615.08) 2128.59,611.67 ccw(c2125.17,615.08) 2130,615.08 2130,626.52 ccw(c2122.5,626.52) 2122.5,634.02 2068.39,634.02 cw(c2068.39,641.52) 2068.39,649.02 2122.5,649.02 ccw(c2122.5,656.52) 2122.5,664.02 2067.5,664.02 cw(c2067.5,671.52) 2067.5,679.02 2122.5,679.02 ccw(c2122.5,686.52) 2122.5,694.02 2080.11,694.02 cw(c2080.11,701.52) 2080.11,709.02 2122.5,709.02 ccw(c2122.5,716.52) 2130,716.52 2130,826.46 2142.82,839.28 2142.82,1221.64 ccw(c2138.01,1221.64) 2141.41,1225.05 ccw(c2138.01,1221.64) 2138.01,1226.46 2128.14,1226.46 ccw(c2128.14,1218.88) 2122.78,1224.24 ccw(c2129.49,1217.52) 2120,1217.52 2120,1195.6 cw(c2110,1195.6) 2117.07,1188.53 cw(c2112.07,1193.53) 2112.07,1186.46 cw(c2112.07,1203.53) 2100,1191.46 cw(c2112.07,1203.53) 2095,1203.53 2095,1206.3 cw(c2095.38,1206.3) 2095.11,1206.57 cw(c2112.07,1208.53) 2095,1208.53 2095,1235.11 ccw(c2073.92,1235.11) 2088.83,1250.01 ccw(c2079.59,1240.78) 2079.59,1253.84 ccw(c2074.6,1241.46) 2069.61,1253.84 2044.47,1253.84 cw(c2044.47,1258.31) 2041.31,1255.15 cw(c2044.47,1258.31) 2040,1258.31 2040,1301.46 cw(c2052.07,1289.39) 2052.07,1306.46 2110,1306.46 ccw(c2131.38,1327.84) 2131.38,1297.6 2136.14,1297.6 ccw(c2143.27,1329.73) 2143.27,1296.82 v1(2153.29,1296.82)
SCKP: R13.1 U2.AC12 UD2.J3 | length 1695
  Top Layer w3.7: v1(2165,1266.46) 2165,1285.96 ccw(c2155,1296.46) 2165,1306.96 U2.AC12@2165,1344.96
  Bottom Layer w3.7: v1(2165,1266.46) cw(c2165,1278.53) 2156.46,1269.99 2145,1281.46 ccw(c2132.93,1269.39) 2132.93,1286.46 2121.77,1286.46 cw(c2121.77,1314.87) 2101.68,1294.78 ccw(c2097.63,1290.73) 2097.63,1296.46 2051.85,1296.46 ccw(c2051.85,1291.99) 2048.69,1295.15 ccw(c2051.09,1292.75) 2047.7,1292.75 2047.7,1267.09 ccw(c2055.55,1267.09) 2050,1261.54 2068.3,1261.54 cw(c2074.6,1241.46) 2081.07,1261.49 cw(c2079.59,1240.78) 2094.27,1255.46 cw(c2073.92,1235.11) 2102.67,1236.46 2150,1236.46 ccw(c2150,1248.53) 2158.54,1239.99 ccw(c2155,1243.53) 2160,1243.53 2160.93,1244.46 cw(c2165,1240.39) 2165,1246.14 cw(c2165,1240.39) 2169.07,1244.46 ccw(c2171.32,1246.71) 2171.32,1243.53 2185,1243.53 cw(c2187.6,1240.92) 2187.6,1244.61 cw(c2187.6,1238.82) 2191.69,1242.91 2192.62,1241.99 2192.62,1227.77 cw(c2183.68,1227.77) 2190,1221.46 cw(c2177.93,1233.53) 2177.93,1216.46 2156.04,1216.46 ccw(c2156.04,1213.96) 2154.27,1215.72 ccw(c2156.04,1213.96) 2153.54,1213.96 ccw(c2160.82,1206.67) 2150.52,1206.67 2150.52,1188.25 ccw(c2153.06,1188.25) 2151.26,1186.46 2151.26,836.41 2138,823.14 2138,750.51 ccw(c2145.5,750.51) 2145.5,743.01 2179.68,743.01 cw(c2179.68,735.51) 2179.68,728.01 2145.5,728.01 ccw(c2145.5,720.51) 2145.5,713.01 2193.68,713.01 cw(c2193.68,705.51) 2193.68,698.01 2145.5,698.01 ccw(c2145.5,690.51) 2145.5,683.01 2193.68,683.01 cw(c2193.68,675.51) 2193.68,668.01 2145.5,668.01 ccw(c2145.5,660.51) 2145.5,653.01 2180.44,653.01 cw(c2180.44,645.51) 2180.44,638.01 2145.5,638.01 ccw(c2145.5,630.51) 2138,630.51 2138,623.46 ccw(c2147.48,627.38) 2143.55,617.91 2156.9,617.91 cw(c2156.9,598.36) 2170.72,612.18 2170.72,604.04 cw(c2152.42,604.04) 2165.36,591.09 2151.96,577.69 v1(2151.96,570.47) 2151.96,564.5 2177.08,539.38 2177.08,443.75 R13.1@2184.37,436.46
SCS0: U2.W13 UD2.L3 | length 1692.2
  Top Layer w5: v1(2192,503.21) 2189.78,505.44 2189.78,559.07 UD2.L3@2201.18,570.47
  Bottom Layer w5: v1(2190.59,1452.32) 2200.59,1462.32 2459.59,1462.32 2564,1357.91 2564,608.73 cw(c2555,608.73) 2561.36,602.36 2433.78,474.78 cw(c2427.42,481.15) 2427.42,472.15 2334.93,472.15 ccw(c2334.93,469.3) 2332.09,469.3 cw(c2329.24,469.3) 2329.24,466.46 2314.93,466.46 cw(c2314.93,469.3) 2312.09,469.3 ccw(c2309.24,469.3) 2309.24,472.15 2223.07,472.15 v1(2192,503.21)
SCS1: U2.Y14 UD2.L4 | length 1695.8
  Bottom Layer w5: v1(2201.18,596.97) 2201.18,565.28 2215,551.46 2215,530.15 2245.15,500 ccw(c2268.93,523.79) 2268.93,490.15 2399.48,490.15 ccw(c2399.48,548.6) 2400.49,490.16 ccw(c2400.89,499.15) 2400.89,490.15 2402.69,490.15 ccw(c2402.69,499.15) 2404.75,490.39 ccw(c2399.48,548.6) 2440.81,507.27 2457.93,524.39 ccw(c2455.43,526.89) 2457.93,529.39 cw(c2460.43,531.89) 2457.93,534.39 2463.54,539.99 cw(c2466.04,537.49) 2468.54,539.99 ccw(c2471.04,542.49) 2473.54,539.99 2479.14,545.6 ccw(c2476.64,548.1) 2479.14,550.6 cw(c2481.64,553.1) 2479.14,555.6 2484.75,561.21 cw(c2487.25,558.71) 2489.75,561.21 ccw(c2492.25,563.71) 2494.75,561.21 2500.36,566.81 ccw(c2497.86,569.31) 2500.36,571.81 cw(c2502.86,574.31) 2500.36,576.81 2505.96,582.42 cw(c2508.46,579.92) 2510.96,582.42 ccw(c2513.46,584.92) 2515.96,582.42 ; v1(2221.18,1421.73) 2225.28,1421.73 2235,1431.46 2450,1431.46 2534.97,1346.48 2534.97,924.63 2542,917.6 ccw(c2544,917.6) 2544,915.6 cw(c2544,913.6) 2546,913.6 2546,897.6 cw(c2544,897.6) 2544,895.6 2538.5,895.6 ccw(c2538.5,892.1) 2535,892.1 2535,879.1 ccw(c2538.5,879.1) 2538.5,875.6 2544,875.6 cw(c2544,873.6) 2546,873.6 2546,857.6 cw(c2544,857.6) 2544,855.6 2538.5,855.6 ccw(c2538.5,852.1) 2535,852.1 2535,839.1 ccw(c2538.5,839.1) 2538.5,835.6 2544,835.6 cw(c2544,833.6) 2546,833.6 2546,817.6 cw(c2544,817.6) 2544,815.6 2538.5,815.6 ccw(c2538.5,812.1) 2535,812.1 2535,799.1 ccw(c2538.5,799.1) 2538.5,795.6 2544,795.6 cw(c2544,793.6) 2546,793.6 2546,777.6 cw(c2544,777.6) 2544,775.6 2538.5,775.6 ccw(c2538.5,772.1) 2535,772.1 2535,759.1 ccw(c2538.5,759.1) 2538.5,755.6 2544,755.6 cw(c2544,753.6) 2546,753.6 2546,737.6 cw(c2544,737.6) 2544,735.6 2538.5,735.6 ccw(c2538.5,732.1) 2535,732.1 2535,719.1 ccw(c2538.5,719.1) 2538.5,715.6 2544,715.6 cw(c2544,713.6) 2546,713.6 2546,697.6 cw(c2544,697.6) 2544,695.6 2538.5,695.6 ccw(c2538.5,692.1) 2535,692.1 2535,679.1 ccw(c2538.5,679.1) 2538.5,675.6 2544,675.6 cw(c2544,673.6) 2546,673.6 2546,657.6 cw(c2544,657.6) 2544,655.6 2538.5,655.6 ccw(c2538.5,652.1) 2535,652.1 2535,639.1 ccw(c2538.5,639.1) 2538.5,635.6 cw(c2538.5,632.1) 2542,632.1 2542,608.46 2517.5,583.96
SDC0-CLK: R23.2 U3.5 | length 1254
  Top Layer w5: U3.5@444.64,2512.8 445,2512.44 v2(445,2426.46)
  Bottom Layer w5: v2(445,2426.46) 445,2346.46 462.61,2328.84 ccw(c469.68,2335.91) 476.76,2328.84 477.61,2329.7 cw(c484.68,2322.63) 491.76,2315.56 490.9,2314.7 ccw(c497.97,2307.63) 505.04,2300.56 505.9,2301.42 cw(c512.97,2294.35) 520.04,2287.27 519.18,2286.42 ccw(c526.25,2279.35) 533.32,2272.27 534.18,2273.13 cw(c541.25,2266.06) 548.32,2258.99 547.47,2258.13 ccw(c554.54,2251.06) 561.61,2243.99 562.47,2244.85 cw(c569.54,2237.78) 576.61,2230.71 575.75,2229.85 ccw(c582.82,2222.78) 589.89,2215.71 590.75,2216.56 cw(c597.82,2209.49) 604.89,2202.42 604.03,2201.56 ccw(c611.11,2194.49) 604.03,2187.42 639.88,2151.58 R23.2@1325.54,2151.58
SDC0-CMD: R27.1 U2.G3 U3.3 | length 2125.4
  Top Layer w5: v2(355,2421.46) 355,2506.46 v2(360,2511.46)
  Bottom Layer w5: R27.1@325.1,2637.19 360,2602.3 v2(360,2511.46) ; v2(355,2421.46) 355,2351.46 590,2116.46 1435,2116.46 1795,1756.46 1921.72,1756.46 v1(1928.79,1749.39)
